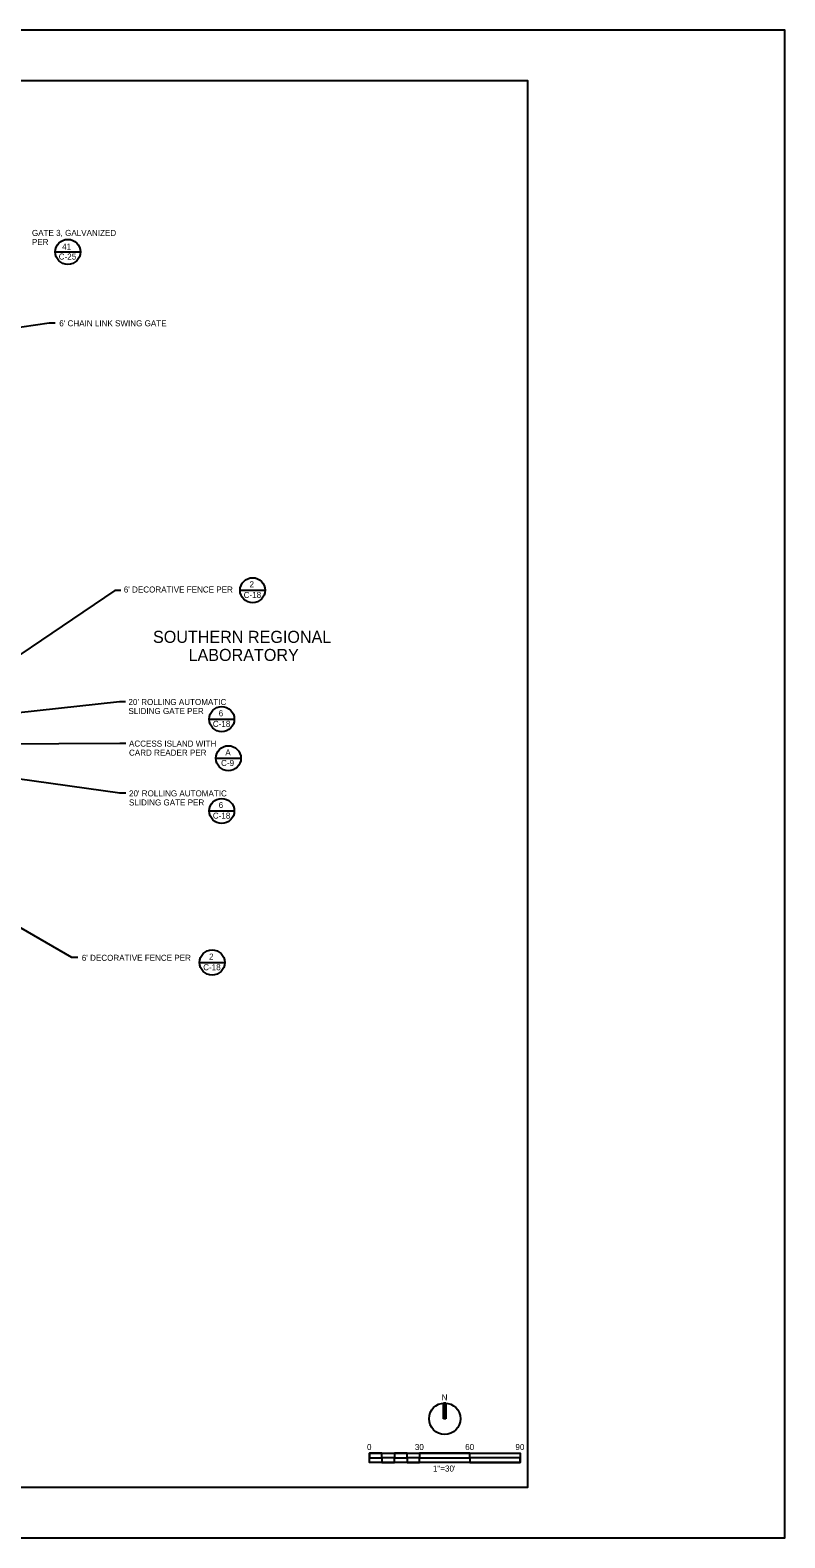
# Model space of a CAD drawing. Extents: x 0 to 3.5, y 0 to 2.5.
# Drawn here: x 2.248 to 3.5, y 0 to 2.5 of the extents above; entities that cross this region are included whole.
import ezdxf

# ---------------------------------------------------------------- set-up
doc = ezdxf.new("R2010")
doc.units = 0
for name, color, linetype in [('C-MARK', 7, 'Continuous'), ('C-TEXT', 7, 'Continuous'), ('C-TEXT-TITL', 7, 'Continuous'), ('G-SYMB', 7, 'Continuous'), ('G-TEXT', 7, 'Continuous'), ('G-TTLB-OTLN', 7, 'Continuous'), ('G-TTLB-VIEW', 7, 'Continuous')]:
    doc.layers.add(name, color=color, linetype=linetype)

msp = doc.modelspace()

# ---------------------------------------------------------------- linework, layer by layer
at = {"layer": 'C-MARK'}
for p, q in [((2.2899, 2.1323), (2.3316, 2.1323)), ((2.5964, 1.5713), (2.6381, 1.5713)), ((2.5452, 1.3575), (2.5869, 1.3575)), ((2.5563, 1.2927), (2.598, 1.2927)), ((2.5452, 1.2053), (2.5869, 1.2053)), ((2.5292, 0.954), (2.5709, 0.954))]:
    msp.add_line(p, q, dxfattribs=at)
for points in [[(2.29, 2.0142), (2.28, 2.0142), (2.1431, 1.9941)], [(2.3985, 1.5709), (2.3885, 1.5709), (2.1092, 1.3821)], [(2.4063, 1.386), (2.3963, 1.386), (2.0568, 1.3491)], [(2.4072, 1.3169), (2.3972, 1.3169), (2.0929, 1.3154)], [(2.4072, 1.2349), (2.3972, 1.2349), (2.0568, 1.2825)], [(2.3274, 0.9621), (2.3174, 0.9621), (2.1591, 1.0535)]]:
    msp.add_lwpolyline(points, dxfattribs=at)
for centre in [(2.3108, 2.1323), (2.6172, 1.5713), (2.5661, 1.3575), (2.5771, 1.2927), (2.5661, 1.2053), (2.5501, 0.954)]:
    msp.add_circle(centre, 0.0208, dxfattribs=at)
at = {"layer": 'G-SYMB'}
for p, q in [((2.934, 0.1975), (2.934, 0.2233)), ((2.9354, 0.1975), (2.9354, 0.2233)), ((2.9363, 0.1975), (2.9363, 0.2233)), ((2.9377, 0.2233), (2.9377, 0.1975)), ((2.9377, 0.1975), (2.934, 0.1975))]:
    msp.add_line(p, q, dxfattribs=at)
for points in [[(2.8109, 0.1328), (2.8317, 0.1328), (2.8317, 0.1406), (2.8109, 0.1406)], [(2.8109, 0.1406), (3.0609, 0.1406), (3.0609, 0.1249), (2.8109, 0.1249)], [(2.8317, 0.1249), (2.8525, 0.1249), (2.8525, 0.1328), (2.8317, 0.1328)], [(2.8525, 0.1328), (2.8734, 0.1328), (2.8734, 0.1406), (2.8525, 0.1406)], [(2.8734, 0.1249), (2.8942, 0.1249), (2.8942, 0.1328), (2.8734, 0.1328)], [(2.8942, 0.1328), (2.9775, 0.1328), (2.9775, 0.1406), (2.8942, 0.1406)], [(2.9775, 0.1249), (3.0609, 0.1249), (3.0609, 0.1328), (2.9775, 0.1328)]]:
    msp.add_lwpolyline(points, close=True, dxfattribs=at)
msp.add_circle((2.9359, 0.1975), 0.026, dxfattribs=at)
msp.add_arc((2.9359, 0.1986), 0.0248, 85.7578, 94.2422, dxfattribs=at)
at = {"layer": 'G-TTLB-OTLN'}
msp.add_lwpolyline([(0, 0), (3.5, 0), (3.5, 2.5), (0, 2.5)], close=True, dxfattribs=at)
at = {"layer": 'G-TTLB-VIEW'}
msp.add_lwpolyline([(0.1667, 2.4167), (3.0729, 2.4167), (3.0729, 0.0833), (0.1667, 0.0833)], close=True, dxfattribs=at)

# ---------------------------------------------------------------- texts
at = {"layer": 'C-TEXT'}
for s, p in [('GATE 3, GALVANIZED', (2.2512, 2.1588)), ('PER', (2.2512, 2.1438)), ('C-25', (2.2956, 2.1196)), ('41', (2.3014, 2.1361)), ("6' CHAIN LINK SWING GATE", (2.2966, 2.0089)), ("6' DECORATIVE FENCE PER", (2.4036, 1.5675)), ('2', (2.6121, 1.5761)), ('C-18', (2.6024, 1.5585)), ('SLIDING GATE PER ', (2.4113, 1.366)), ("20' ROLLING AUTOMATIC", (2.4113, 1.381)), ('C-18', (2.5513, 1.3447)), ('6', (2.561, 1.3623)), ('ACCESS ISLAND WITH', (2.4122, 1.312)), ('CARD READER PER', (2.4122, 1.297)), ('A', (2.572, 1.2974)), ('C-9', (2.5649, 1.2799)), ("20' ROLLING AUTOMATIC", (2.4122, 1.2294)), ('SLIDING GATE PER', (2.4122, 1.2144)), ('C-18', (2.5513, 1.1926)), ('6', (2.561, 1.2101)), ("6' DECORATIVE FENCE PER", (2.334, 0.9568)), ('C-18', (2.5353, 0.9412)), ('2', (2.545, 0.9588))]:
    msp.add_text(s, height=0.01, dxfattribs=at).set_placement(p)
at = {"layer": 'C-TEXT-TITL'}
for s, p in [('SOUTHERN REGIONAL', (2.452, 1.484)), ('LABORATORY', (2.511, 1.454))]:
    msp.add_text(s, height=0.02, dxfattribs=at).set_placement(p)
at = {"layer": 'G-SYMB'}
msp.add_text('N', height=0.01, dxfattribs=at).set_placement((2.9308, 0.2278))
at = {"layer": 'G-TEXT'}
for s, p in [('0', (2.807, 0.1456)), ('30', (2.8864, 0.1456)), ('60', (2.9698, 0.1456)), ('90', (3.0531, 0.1456)), ('1"=30\'', (2.9163, 0.1099))]:
    msp.add_text(s, height=0.01, dxfattribs=at).set_placement(p)

doc.saveas('drawing.dxf')
